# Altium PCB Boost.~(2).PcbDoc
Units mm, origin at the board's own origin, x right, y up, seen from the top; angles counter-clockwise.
Board outline 31.77 x 30.5 mm, 2 copper layers (Top Layer, Bottom Layer); 19 components, 9 nets, 53 pads, 9 vias.
Unrouted connection lines stored in the file: 2.
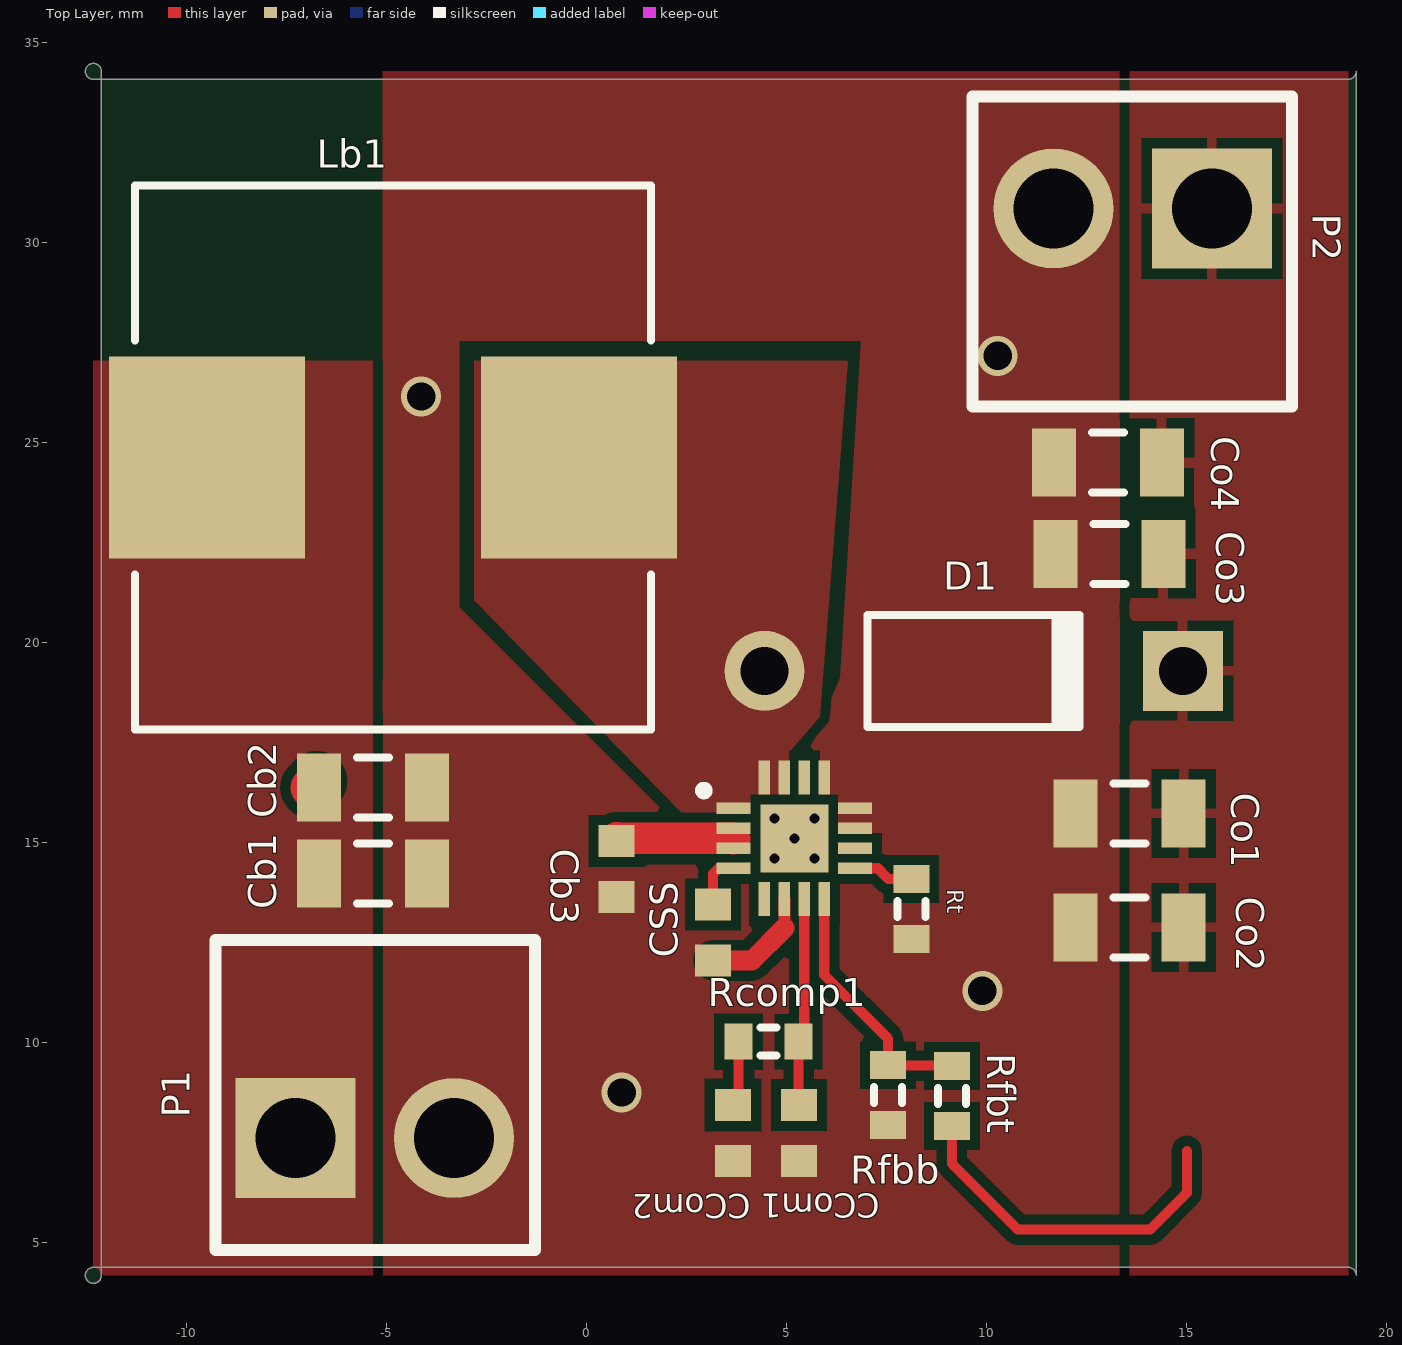
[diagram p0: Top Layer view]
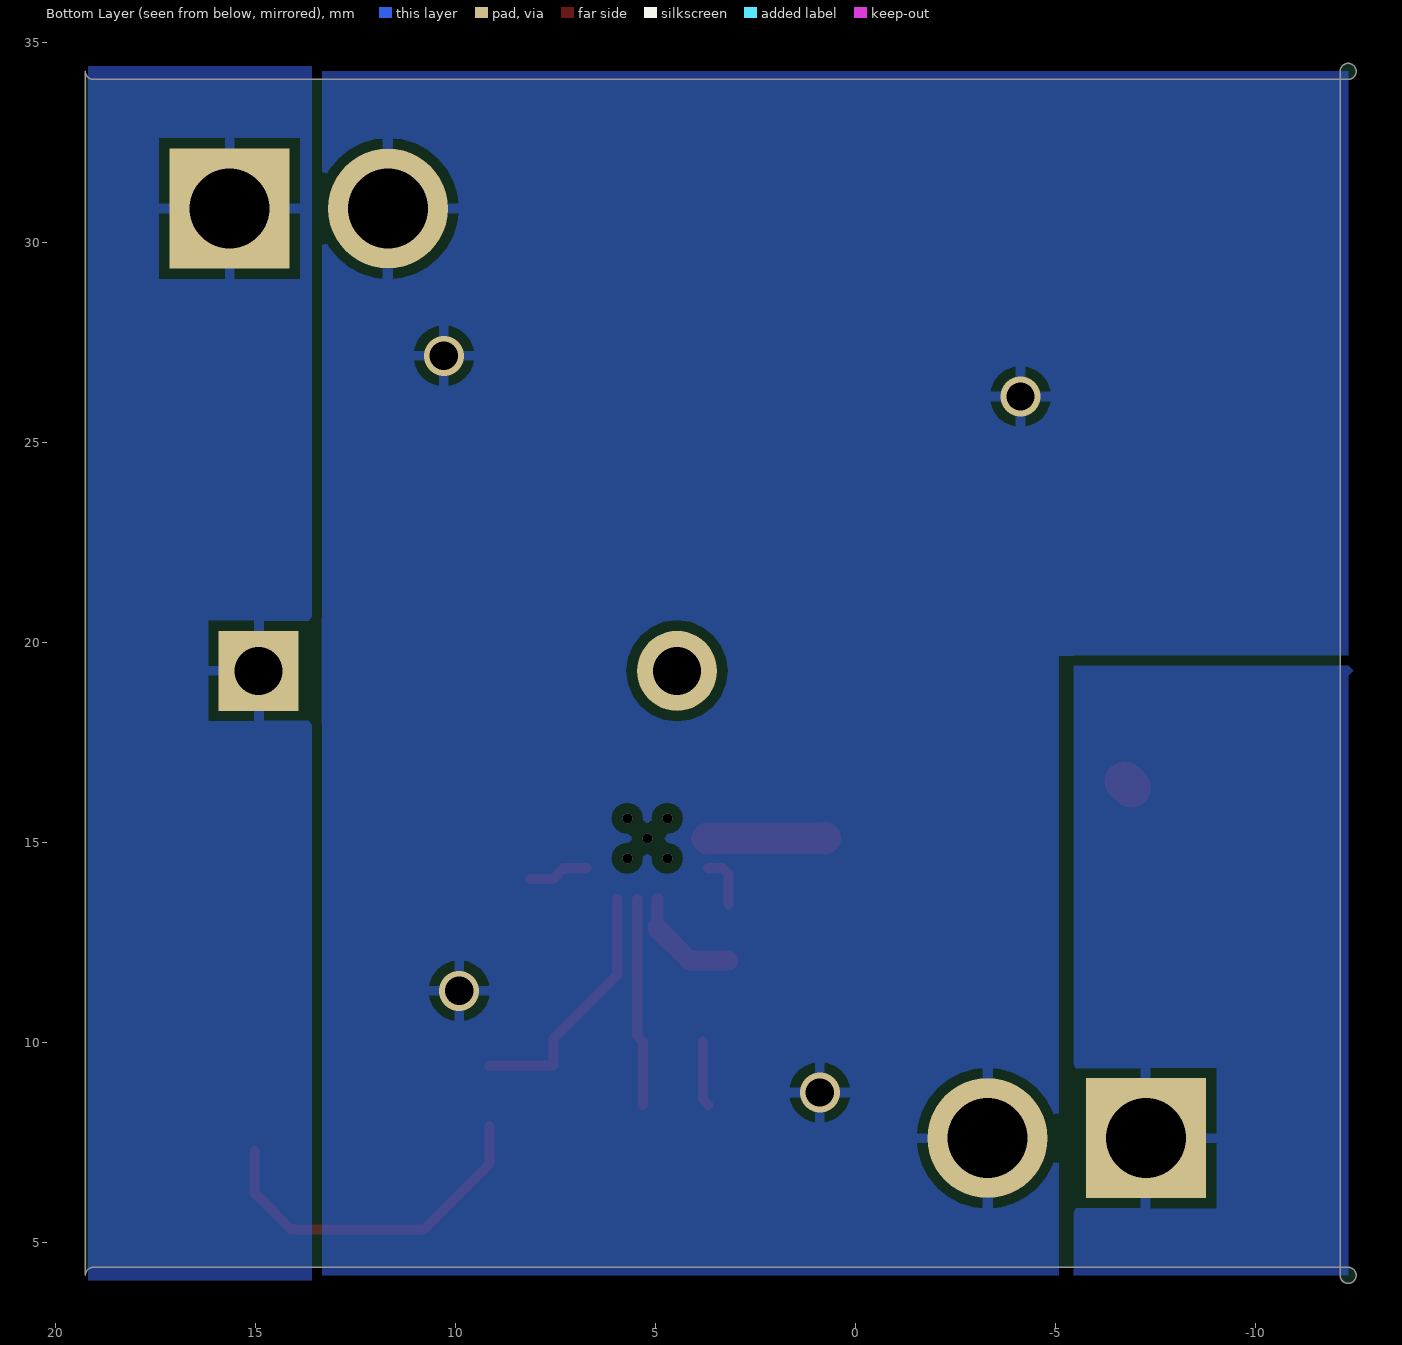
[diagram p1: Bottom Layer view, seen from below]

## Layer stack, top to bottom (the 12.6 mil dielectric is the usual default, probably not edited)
Top Solder: solder mask 0.0102, Solder Resist, Dk 3.5
Top Layer: signal copper 0.0356
Dielectric 1: dielectric 0.32, FR-4, Dk 4.8
Bottom Layer: signal copper 0.0356
Bottom Solder: solder mask 0.0102, Solder Resist, Dk 3.5

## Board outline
-12.319,3.991 cw(c-12.319,4.191) -12.519,4.191 cw(c-12.319,4.191) -12.319,4.391 19.05,4.391 cw(c19.05,4.191) 19.25,4.191 19.25,34.29 cw(c19.05,34.29) 19.05,34.09 -12.319,34.09 cw(c-12.319,34.29) -12.519,34.29 cw(c-12.319,34.29) -12.319,34.49 cw(c-12.319,34.29) -12.119,34.29 -12.119,4.191 cw(c-12.319,4.191)

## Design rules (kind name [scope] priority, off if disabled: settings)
Clearance [All] p1: gap=0.254 ignorepadtopadclearanceinfootprint=FALSE except(0: Arc-Hole Track-Hole SMDPad-Hole THPad-Hole Via-Hole Fill-Hole Poly-Hole Region-Hole Text-Hole; 0.1: Arc-Arc Arc-Track Arc-SMDPad Track-Track Track-SMDPad SMDPad-SMDPad)
PlaneConnect [All] p1: planeconnectstyle=Direct reliefexpansion=0.508 reliefentries=4 reliefconductorwidth=0.254 reliefairgap=0.254
PolygonConnect [All] p1: connectstyle=Direct reliefconductorwidth=0.254 reliefentries=4 polygonreliefangle="90 Angle" airgapwidth=0.254
RoomDefinition Boost [InComponentClass('Boost')] p1: confinementstyle=ConfineIn formatcopy=TRUE lockcomponents=FALSE outline -77.851,-73.914 -27.051,-73.914 -27.051,-48.514 -77.851,-48.514
RoutingVias [All] p1: holewidth=0.711 width=1.27 viastyle="Through Hole" minholewidth=0.711 minwidth=1.27 maxholewidth=0.711 maxwidth=1.27
SolderMaskExpansion [All] p1: expansion=0.102
Width [All] p1: maxlimit=0.254 minlimit=0.254 preferedwidth=0.254
29 further rules are at their usual default settings.

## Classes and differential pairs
component class Boost: Cb1 Cb2 Cb3 CCom1 CCom2 Co1 Co2 Co3 Co4 CSS D1 Lb1 P1 P2 Rcomp1 Rfbb Rfbt Rt

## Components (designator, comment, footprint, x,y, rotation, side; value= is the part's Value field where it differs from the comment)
Cb1 "capacitor,100nF,10%,16V,X7R,0603" C1206 -5.334,14.233 r0 top value=10uF
Cb2 "capacitor,100nF,10%,16V,X7R,0603" C1206 -5.334,16.383 r180 top value=100nF
Cb3 "capacitor,100nF,10%,16V,X7R,0603" 1608[0603] 0.762,14.351 r270 top value=0.1uF
CCom1 "capacitor,100nF,10%,16V,X7R,0603" 1608[0603] 5.322,7.747 r90 top value=430pF
CCom2 "capacitor,100nF,10%,16V,X7R,0603" 1608[0603] 3.671,7.747 r90 top value=22nF
Co1 "capacitor,100nF,10%,16V,X7R,0603" C1206 13.589,15.74 r180 top value=4.7uF
Co2 "capacitor,100nF,10%,16V,X7R,0603" C1206 13.589,12.891 r180 top value=4.7uF
Co3 "capacitor,100nF,10%,16V,X7R,0603" C1206 13.081,22.225 r180 top value=4.7uF
Co4 "capacitor,100nF,10%,16V,X7R,0603" C1206 13.043,24.511 r180 top value=22uF
CSS "capacitor,100nF,10%,16V,X7R,0603" 1608[0603] 3.175,12.764 r90 top value=22nF
D1 "Diode 1N4001" DO-41 9.688,19.304 r0 top
Lb1 "BOURNS  SRU8028A-220Y NDUCTOR 22 µH" IHLP-5050CE-01 -4.826,24.638 r0 top value=6.8uH
P1 "Header 2" soket2x3.96mm -7.262,7.62 r0 top
P2 "Header 2" soket2x3.96mm 15.644,30.861 r180 top
Rcomp1 "3.24k 0603" J1-0603 4.56,10.033 r180 top value=1K
Rfbb "10k 0603" J1-0603 7.549,8.694 r90 top
Rfbt "187k 0603" J1-0603 9.144,8.673 r270 top
Rt "86.6k" J1-0603 8.128,13.347 r270 top value=1K
? "tps55340" TPS55340 5.203,15.117 r0 top

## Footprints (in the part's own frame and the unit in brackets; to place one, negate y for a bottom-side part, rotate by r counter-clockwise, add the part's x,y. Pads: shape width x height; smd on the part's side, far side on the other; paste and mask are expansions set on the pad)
1608[0603] [mm] "Chip Capacitor, Body 1.6x0.8mm, IPC High Density"
  rect 0.8x0.9 smd: 1(-0.7,0) 2(0.7,0)
  body extent -0.87,-0.48 0.87,0.48, height 1.3
C1206 [mm] "Chip Capacitor, Body 3.2x1.6mm, IPC High Density"
  rect 1.1x1.7 smd: 1(-1.35,0) 2(1.35,0)
  silkscreen extent -0.4,-0.75 0.4,0.75, body extent -1.7,-0.9 1.7,0.9, height 1.3
DO-41 [mm] "Diode, Axial; Body 5.2 x 2.7 mm (LxDia. max), Lead Dia. 0.86 mm (max)"
  round 2 hole 1.2: 1(-5.23,0)
  rect 2x2 hole 1.2: 2(5.23,0)
  silkscreen extent -2.65,-1.4 2.75,1.4
IHLP-5050CE-01 [mm] "Precision Wire Wound Inductor, 2-Leads, Body 12,90x13,20mm, IPC Medium Density"
  rect 4.9x5.05 smd: 1(-4.65,0) 2(4.65,0)
  silkscreen extent -6.45,-6.8 6.45,6.8, body extent -6.45,-6.79 6.45,6.79, height 3.5
J1-0603 [mm] "Chip Resistor, Body 1.6x0.8mm, IPC High Density"
  rect 0.7x0.9 smd: 1(-0.75,0) 2(0.75,0)
  silkscreen extent -0.2,-0.35 0.2,0.35, body extent -0.85,-0.48 0.85,0.48, height 0.9
soket2x3.96mm [mm] "2 way friction lock header,3.96mm pitch"
  rect 3x3 hole 2: 1(0,0)
  round 3 hole 2: 2(3.96,0)
  silkscreen extent -2,-2.8 5.98,4.95, body extent -2.03,-2.92 5.97,5.08, height 13.32
TPS55340 [mm]
  rect 1.7x1.7 smd mask+0.07: 0(0,0)
  rect 0.85x0.28 smd mask+0.07: 1(-1.52,0.75) 2(-1.52,0.25) 3(-1.52,-0.25) 4(-1.52,-0.75) 9(1.52,-0.75) 10(1.52,-0.25) 11(1.52,0.25) 12(1.52,0.75)
  rect 0.28x0.85 smd mask+0.07: 5(-0.75,-1.52) 6(-0.25,-1.52) 7(0.25,-1.52) 8(0.75,-1.52) 13(0.75,1.52) 14(0.25,1.52) 15(-0.25,1.52) 16(-0.75,1.52)
  silkscreen extent -2.35,1.1 -2.17,1.29

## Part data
Cb1 Cb2 Cb3 CCom1 CCom2 Co1 Co2 Co3 Co4 CSS: library part "Cap Semi", "Capacitor (Semiconductor SIM Model)"
D1: "1 Amp General Purpose Rectifier"
Lb1: library part "Inductor Iron", "Magnetic-Core Inductor"
P1 P2: "Header, 2-Pin"
Rcomp1 Rfbb Rfbt Rt: library part Res3, "Resistor"

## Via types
v1: diameter 0.25, hole 0.25, Top Layer to Bottom Layer, 5 vias
v2: diameter 1, hole 0.711, Top Layer to Bottom Layer, 4 vias

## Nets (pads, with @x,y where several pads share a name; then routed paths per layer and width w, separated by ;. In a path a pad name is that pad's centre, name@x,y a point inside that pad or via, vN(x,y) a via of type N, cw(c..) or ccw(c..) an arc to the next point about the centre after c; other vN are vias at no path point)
FB: ?.8 Rfbb.2 Rfbt.1 | length 6.4
  Top Layer w0.254: ?.8 5.953,11.7 7.549,10.104 Rfbb.2 7.56,9.434 9.134,9.434 Rfbt.1
GND: ?.6 ?.11 ?.12 ?.13 Cb1.2 Cb2.1 Cb3.2 CCom1.1 CCom2.1 Co1.2 Co2.2 Co3.2 Co4.2 CSS.1 P1.2 P2.2 Rfbb.1 Rt.2 | length 2.8
  Top Layer w0.3: 4.953,12.871 ?.6
  Top Layer w0.5: CSS.1 4.145,12.063 4.953,12.871
  other v2: 0.889,8.763 9.906,11.303 -4.128,26.162 10.287,27.178
Net_1: ?.1 ?.15 ?.16 D1.1 Lb1.2
Net_4: ?.4 CSS.2 | length 1.3
  Top Layer w0.254: CSS.2 3.175,14.233 3.309,14.367 ?.4
Net_7: ?.7 CCom1.2 Rcomp1.1 | length 5.2
  Top Layer w0.254: CCom1.2 5.31,8.459 Rcomp1.1 5.453,10.176 ?.7
Net_9: ?.9 Rt.1 | length 1.5
  Top Layer w0.254: ?.9 7.29,14.367 7.56,14.097 Rt.1
NetCCom2_2: CCom2.2 Rcomp1.2 | length 1.6
  Top Layer w0.254: CCom2.2 3.81,8.586 Rcomp1.2
Vin: ?.2 ?.3 Cb1.1 Cb2.2 Cb3.1 Lb1.1 P1.1 | length 3.5
  Top Layer w0.254: Cb3.1@0.712,15.051 Cb3.1
  Top Layer w0.5: 3.682,15.046 3.809,15.11
  Top Layer w0.6: 3.682,15.11 3.684,15.11 3.809,15.11
  Top Layer w0.8: Cb3.1@0.762,15.119 3.682,15.11
  Top Layer w1: Cb2.2@-6.891,16.383 Cb2.2@-6.731,16.543
Vout: Co1.1 Co2.1 Co3.1 Co4.1 D1.2 P2.1 Rfbt.2 | length 8.9
  Top Layer w0.254: Rfbt.2 9.144,6.985 10.795,5.334 14.097,5.334 15.019,6.256 15.019,7.303
pads on no net: ?.0 ?.5 ?.10 ?.14
copper on no net:
  other v1: 4.703,14.617 5.703,14.617 5.203,15.117 4.703,15.617 5.703,15.617

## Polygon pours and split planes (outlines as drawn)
no net on Mechanical 1 (solid): 38.354,-3.048 38.354,33.909 38.354,-3.048 -12.319,-3.048
no net on Mechanical 1 (solid): -12.319,34.29
no net on Mechanical 1 (solid): -12.319,34.29
no net on Mechanical 1 (solid): -12.319,34.29 -12.319,22.098
Net_1 on Top Layer "SW" (solid, pour order 18): 6.541,27.051 -2.794,27.051 -2.794,21.072 2.528,15.621 4.191,15.621 4.191,16.129 5.08,16.129 5.08,17.272 5.842,18.161
GND on Top Layer "Gnd" (solid, pour order 30): -3.175,34.29 7.29,34.29 7.29,27.559 -3.175,27.559
Vout on Top Layer "Vout" (solid, pour order 10): 13.589,4.191 19.05,4.191 19.05,34.29 13.589,34.29
Vin on Top Layer "Vin" (solid, pour order 8): -5.334,27.051 -5.334,4.191 -12.065,4.191 -12.319,4.445 -12.319,27.051
GND on Top Layer "GND" (solid, pour order 24): 13.335,4.191 -5.08,4.191 -5.08,34.29 -3.175,34.29 -3.175,20.891 2.222,15.494 3.295,15.494 4.848,15.606 6.35,19.135 7.29,34.29 13.335,34.29
Vout on Bottom Layer "Vout" (solid, pour order 36): 13.589,34.417 19.177,34.417 19.177,4.064 13.589,4.064
Vin on Bottom Layer "Vin" (solid, pour order 38): -12.319,4.191 -12.319,19.177 -12.446,19.304 -12.319,19.431 -5.461,19.431 -5.461,4.191
no net on Bottom Layer "Bottom Layer-No Net" (solid, pour order 40): -12.319,34.29
GND on Bottom Layer "GND" (solid, pour order 42): -12.319,34.29 -12.319,19.685 -5.08,19.685 -5.08,4.191 13.335,4.191 13.335,34.29 -12.319,34.29

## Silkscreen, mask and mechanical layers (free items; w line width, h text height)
Mechanical 1:
  lines w0.4: -12.319,4.191 19.05,4.191 19.05,34.29 -12.319,34.29 -12.319,19.304 -12.319,4.191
